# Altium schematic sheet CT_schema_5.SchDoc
size 522 x 390 mm
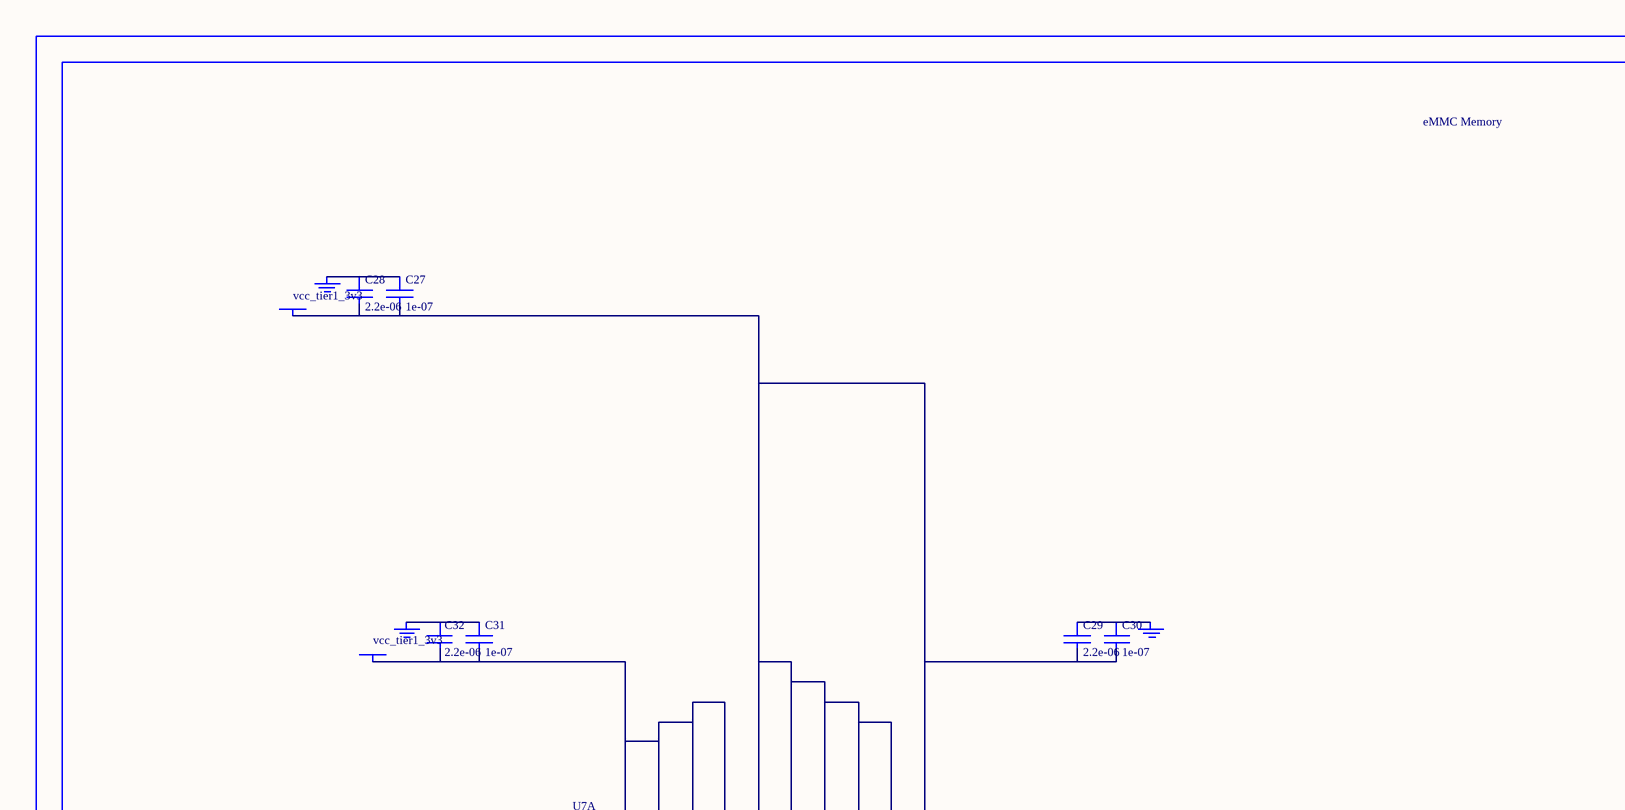
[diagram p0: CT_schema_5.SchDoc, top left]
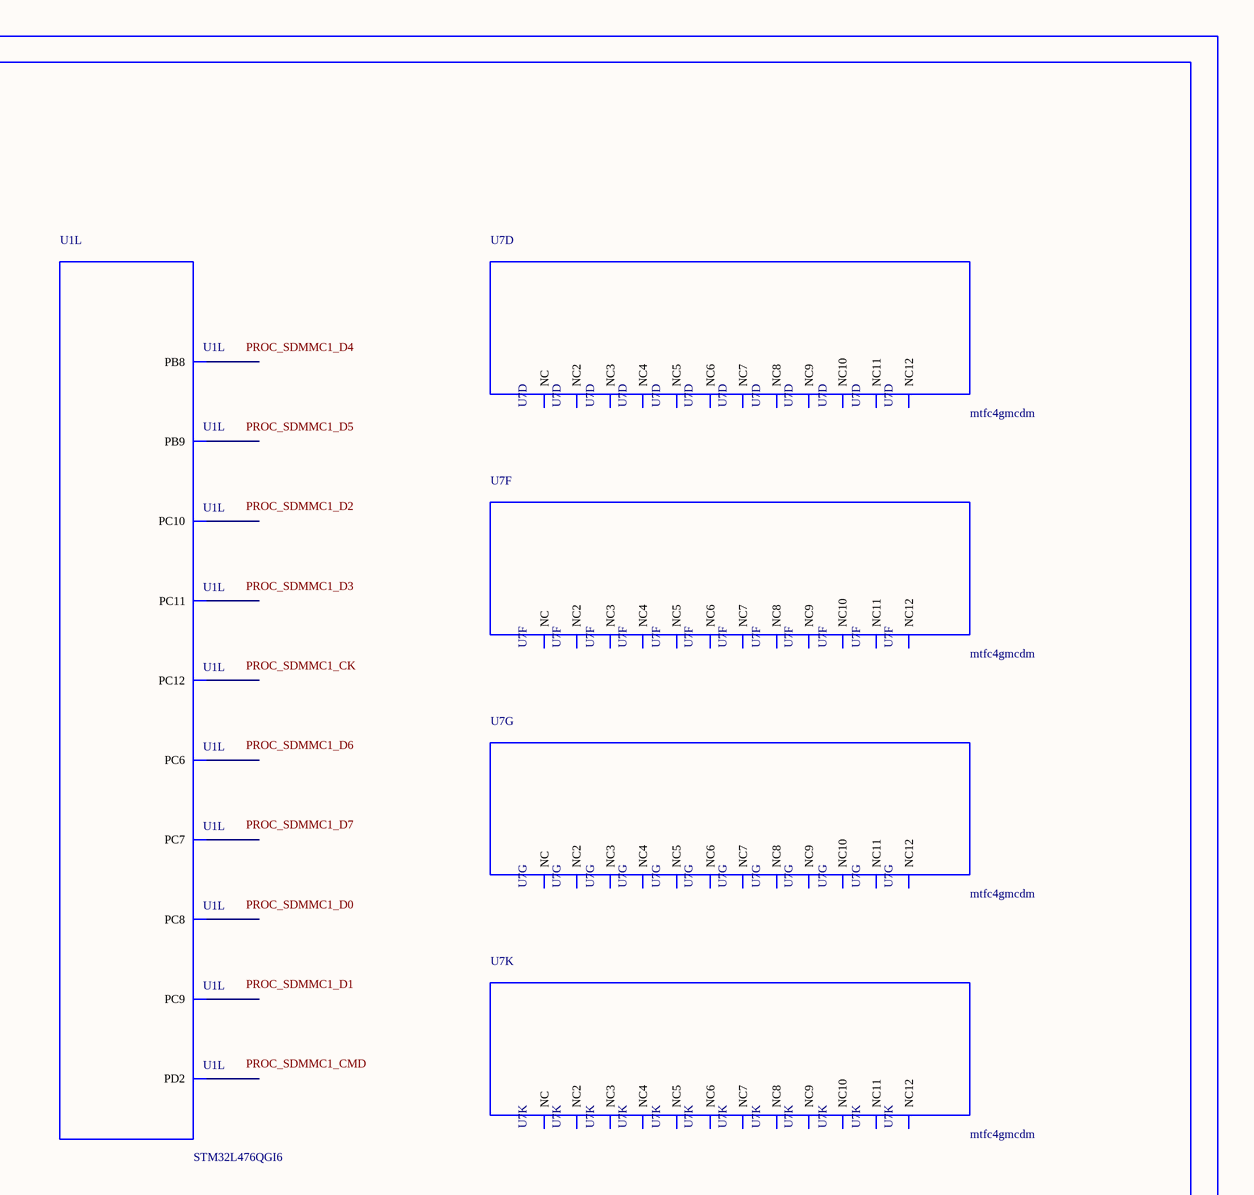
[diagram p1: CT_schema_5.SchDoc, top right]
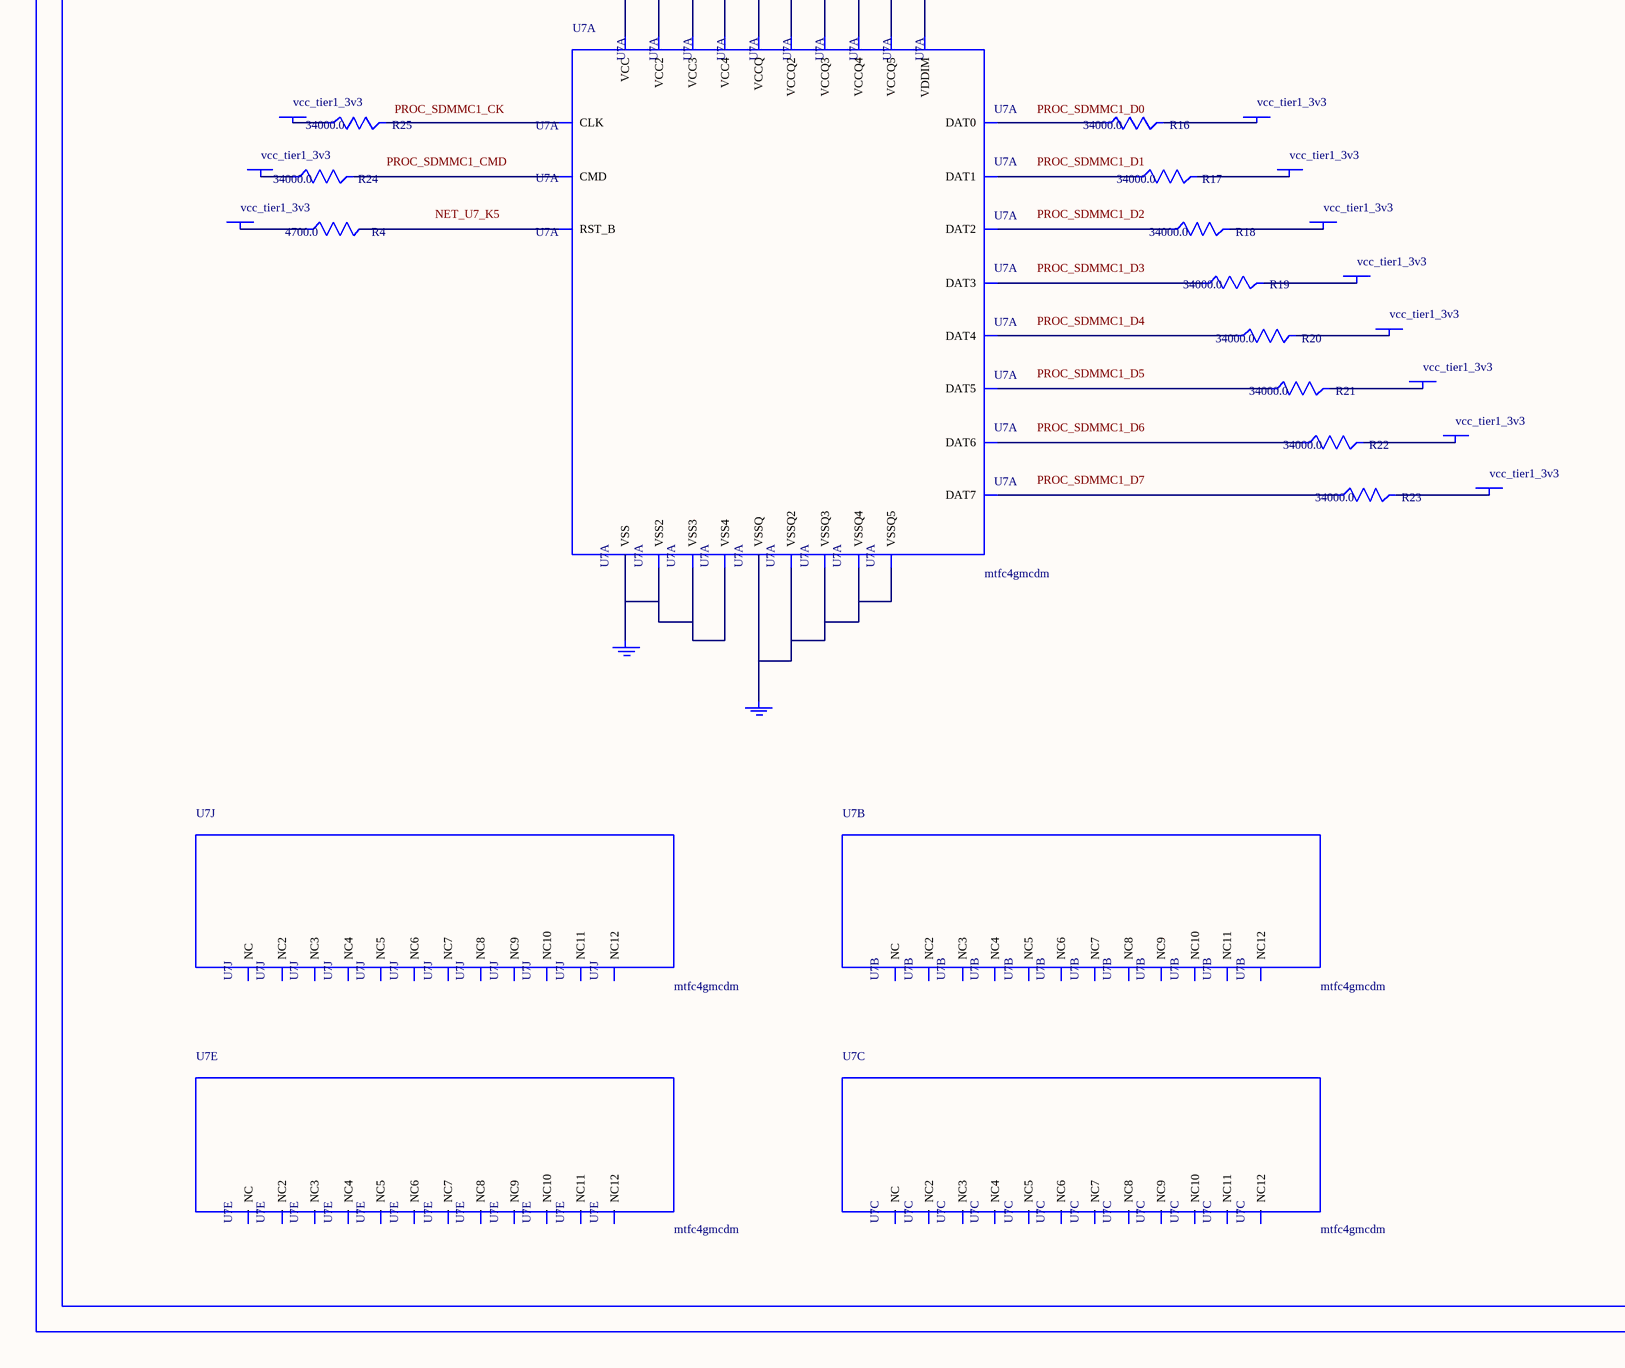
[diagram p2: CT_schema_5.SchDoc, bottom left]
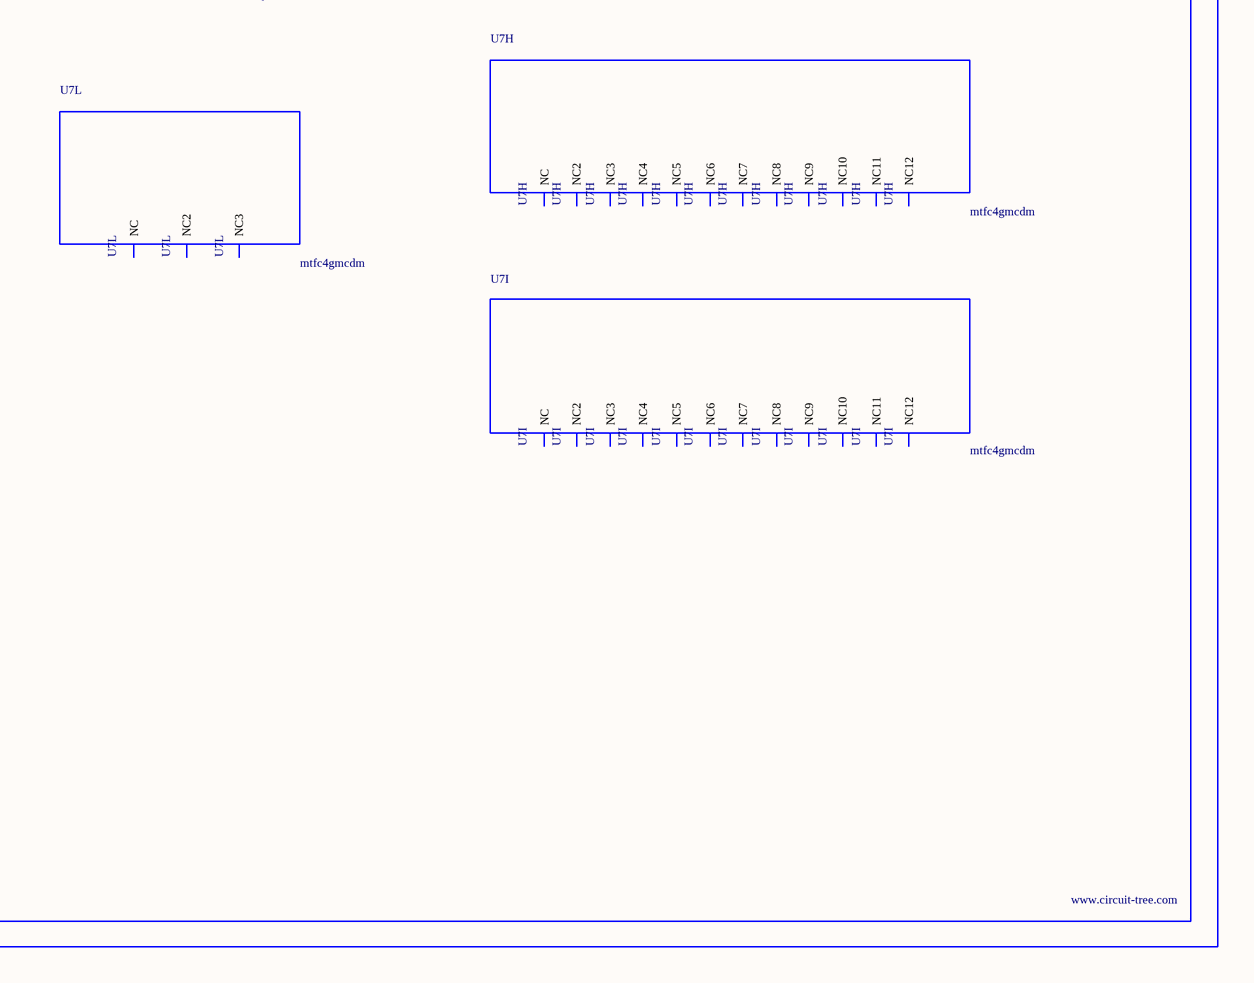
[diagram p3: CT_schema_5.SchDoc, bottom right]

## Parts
BORDER4  (no value)
C27  1e-07  [C0402]
C28  2.2e-06  [C0603]
C29  2.2e-06  [C0603]
C30  1e-07  [C0402]
C31  1e-07  [C0402]
C32  2.2e-06  [C0603]
GND_INSTANCE_4_0  (no value)
GND_INSTANCE_4_1  (no value)
GND_INSTANCE_4_2  (no value)
GND_INSTANCE_4_3  (no value)
GND_INSTANCE_4_4  (no value)
POWER_INSTANCE_4_0  vcc_tier1_3v3
POWER_INSTANCE_4_1  vcc_tier1_3v3
POWER_INSTANCE_4_2  vcc_tier1_3v3
POWER_INSTANCE_4_3  vcc_tier1_3v3
POWER_INSTANCE_4_4  vcc_tier1_3v3
POWER_INSTANCE_4_5  vcc_tier1_3v3
POWER_INSTANCE_4_6  vcc_tier1_3v3
POWER_INSTANCE_4_7  vcc_tier1_3v3
POWER_INSTANCE_4_8  vcc_tier1_3v3
POWER_INSTANCE_4_9  vcc_tier1_3v3
POWER_INSTANCE_4_10  vcc_tier1_3v3
POWER_INSTANCE_4_11  vcc_tier1_3v3
POWER_INSTANCE_4_12  vcc_tier1_3v3
R4  4700.0  [R0603]
R16  34000.0  [R0603]
R17  34000.0  [R0603]
R18  34000.0  [R0603]
R19  34000.0  [R0603]
R20  34000.0  [R0603]
R21  34000.0  [R0603]
R22  34000.0  [R0603]
R23  34000.0  [R0603]
R24  34000.0  [R0603]
R25  34000.0  [R0603]
U1  STM32L476QGI6  [UFBGA132]  (part L of 12)
U7  mtfc4gmcdm  [TFBGA-153]  (parts A,B,C,D,E,F,G,H,I,J,K,L of 12)

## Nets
NetC27_1: C27.1 C28.1 GND_INSTANCE_4_0.0(GND)
NetC27_2: C27.2 C28.2 C29.2 C30.2 POWER_INSTANCE_4_0.0(PWR) U7.C2(VDDIM) U7.C6(VCCQ) U7.M4(VCCQ2) U7.N4(VCCQ3) U7.P3(VCCQ4) U7.P5(VCCQ5)
NetC29_1: C29.1 C30.1 GND_INSTANCE_4_1.0(GND)
NetC31_1: C31.1 C32.1 GND_INSTANCE_4_2.0(GND)
NetC31_2: C31.2 C32.2 POWER_INSTANCE_4_1.0(PWR) U7.E6(VCC) U7.F5(VCC2) U7.J10(VCC3) U7.K9(VCC4)
NetGND_INSTANCE_4_3_0: GND_INSTANCE_4_3.0(GND) U7.E7(VSS) U7.G5(VSS2) U7.H10(VSS3) U7.K8(VSS4)
NetGND_INSTANCE_4_4_0: GND_INSTANCE_4_4.0(GND) U7.C4(VSSQ) U7.N2(VSSQ2) U7.N5(VSSQ3) U7.P4(VSSQ4) U7.P6(VSSQ5)
NetPOWER_INSTANCE_4_2_0: POWER_INSTANCE_4_2.0(PWR) R16.2
NetPOWER_INSTANCE_4_3_0: POWER_INSTANCE_4_3.0(PWR) R17.2
NetPOWER_INSTANCE_4_4_0: POWER_INSTANCE_4_4.0(PWR) R18.2
NetPOWER_INSTANCE_4_5_0: POWER_INSTANCE_4_5.0(PWR) R19.2
NetPOWER_INSTANCE_4_6_0: POWER_INSTANCE_4_6.0(PWR) R20.2
NetPOWER_INSTANCE_4_7_0: POWER_INSTANCE_4_7.0(PWR) R21.2
NetPOWER_INSTANCE_4_8_0: POWER_INSTANCE_4_8.0(PWR) R22.2
NetPOWER_INSTANCE_4_9_0: POWER_INSTANCE_4_9.0(PWR) R23.2
NetPOWER_INSTANCE_4_10_0: POWER_INSTANCE_4_10.0(PWR) R24.1
NetPOWER_INSTANCE_4_11_0: POWER_INSTANCE_4_11.0(PWR) R25.1
NetPOWER_INSTANCE_4_12_0: POWER_INSTANCE_4_12.0(PWR) R4.1
NetR4_2: R4.2 U7.K5(RST_B)
NetR16_1: R16.1 U7.A3(DAT0)
NetR17_1: R17.1 U7.A4(DAT1)
NetR18_1: R18.1 U7.A5(DAT2)
NetR19_1: R19.1 U7.B2(DAT3)
NetR20_1: R20.1 U7.B3(DAT4)
NetR21_1: R21.1 U7.B4(DAT5)
NetR22_1: R22.1 U7.B5(DAT6)
NetR23_1: R23.1 U7.B6(DAT7)
NetR24_2: R24.2 U7.M5(CMD)
NetR25_2: R25.2 U7.M6(CLK)

Not connected (* = marked no-connect by the designer): U1 A3(PB8) B3(PB9) B10(PC12) B11(PC10) C8(PD2) C10(PC11) D12(PC9) E10(PC8) E11(PC7) E12(PC6); U7 A1(NC) A2(NC7) A6(NC8) A7(NC9) A8(NC10) A9(NC11) A10(NC2) A11(NC3) A12(NC4) A13(NC5) A14(NC6) B1(NC12) B7(NC6) B8(NC7) B9(NC8) B10(NC) B11(NC2) B12(NC3) B13(NC4) B14(NC5) C1(NC9) C3(NC10) C5(NC11) C7(NC12) C8(NC6) C9(NC7) C10(NC) C11(NC2) C12(NC3) C13(NC4) C14(NC5) D1(NC8) D2(NC10) D3(NC11) D4(NC12) D12(NC9) D13(NC) D14(NC2) E1(NC3) E2(NC8) E3(NC9) E5(NC10) E8(NC11) E9(NC12) E10(NC4) E12(NC5) E13(NC6) E14(NC7) F1(NC) F2(NC6) F3(NC7) F10(NC2) F12(NC3) F13(NC4) F14(NC5) G1(NC8) G2(NC11) G3(NC12) G10(NC9) G12(NC10) G13(NC) G14(NC2) H1(NC3) H2(NC7) H3(NC8) H5(NC9) H12(NC4) H13(NC5) H14(NC6) J1(NC10) J2(NC11) J3(NC12) J5(NC4) J12(NC) J13(NC2) J14(NC3) K1(NC5) K2(NC9) K3(NC10) K6(NC11) K7(NC12) K10(NC6) K12(NC7) K13(NC8) K14(NC) L1(NC2) L2(NC6) L3(NC7) L12(NC3) L13(NC4) L14(NC5) M1(NC8) M2(NC9) M3(NC10) M7(NC11) M8(NC12) M9(NC6) M10(NC) M11(NC2) M12(NC3) M13(NC4) M14(NC5) N1(NC7) N3(NC8) N6(NC9) N7(NC10) N8(NC11) N9(NC12) N10(NC) N11(NC2) N12(NC3) N13(NC4) N14(NC5) P1(NC6) P2(NC9) P7(NC10) P8(NC11) P9(NC12) P10(NC7) P11(NC8) P12(NC) P13(NC2) P14(NC3)

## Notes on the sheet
- Labels drawn without touching a wire or pin: NET_U7_K5, PROC_SDMMC1_CK, PROC_SDMMC1_CMD, PROC_SDMMC1_D0, PROC_SDMMC1_D1, PROC_SDMMC1_D2, PROC_SDMMC1_D3, PROC_SDMMC1_D4, PROC_SDMMC1_D5, PROC_SDMMC1_D6, PROC_SDMMC1_D7

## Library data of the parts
BORDER4 = BORDER_PAGE4
C27 C30 C31 = C0402C104K3RACTU
C28 C29 C32 = C0603C225K8RACTU
GND_INSTANCE_4_0-GND_INSTANCE_4_4 = GND
POWER_INSTANCE_4_0-POWER_INSTANCE_4_12 = PWR
R4 = RC0603JR-074K7L
R16-R25 = ERA3ARB3402V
